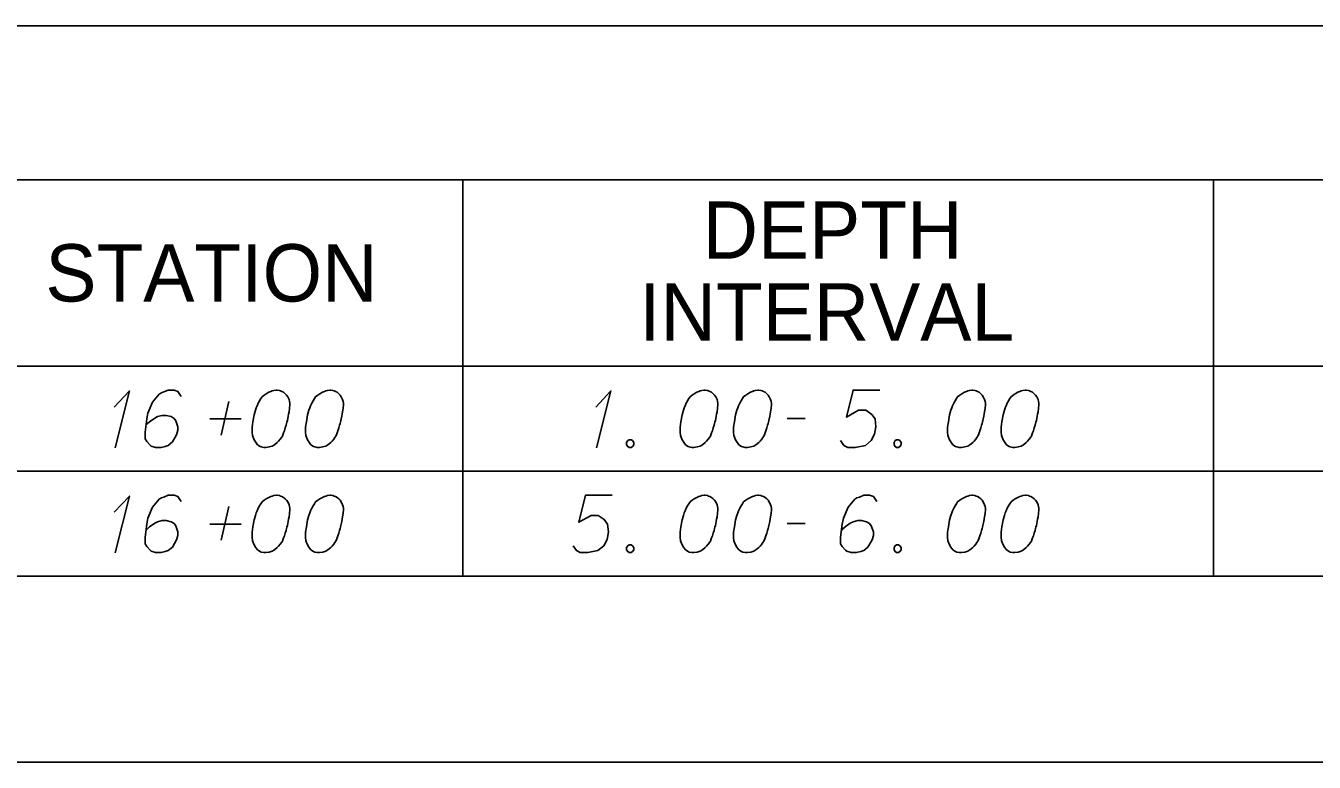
# Model space of a CAD drawing. Extents: x 2074207 to 2076812, y 516372 to 523312.
# Drawn here: x 2076345.6 to 2076453.5, y 516524.4 to 516586.1 of the extents above; entities that cross this region are included whole.
import ezdxf

# ---------------------------------------------------------------- set-up
doc = ezdxf.new("R2010")
doc.units = 0
for name, color, linetype in [('Prop DirtTable_ Soil Test Results - Outline (Major)', 7, 'Continuous'), ('Prop DirtTable_ Soil Test Results - Outline (Minor)', 7, 'Continuous'), ('Prop DirtTable_ Soil Test Results - Tx (Header - Small)', 7, 'Continuous'), ('Prop DirtTable_ Soil Test Results - Tx (Sample Data)', 7, 'Continuous')]:
    doc.layers.add(name, color=color, linetype=linetype)

msp = doc.modelspace()

# ---------------------------------------------------------------- linework, layer by layer
at = {"layer": 'Prop DirtTable_ Soil Test Results - Outline (Major)'}
for p, q in [((2076260.61, 516586.09), (2076811.9, 516586.09)), ((2076260.61, 516557.6), (2076811.9, 516557.6)), ((2076260.61, 516557.6), (2076811.9, 516557.6)), ((2076260.61, 516540), (2076811.9, 516540)), ((2076260.61, 516524.42), (2076811.9, 516524.42))]:
    msp.add_line(p, q, dxfattribs=at)
at = {"layer": 'Prop DirtTable_ Soil Test Results - Outline (Minor)'}
for p, q in [((2076260.61, 516573.2), (2076811.9, 516573.2)), ((2076382.2, 516573.2), (2076382.2, 516548.8)), ((2076445.06, 516573.2), (2076445.06, 516548.8)), ((2076260.61, 516548.8), (2076811.9, 516548.8)), ((2076260.61, 516548.8), (2076811.9, 516548.8)), ((2076382.2, 516548.8), (2076382.2, 516540)), ((2076445.06, 516548.8), (2076445.06, 516540)), ((2076260.61, 516540), (2076811.9, 516540))]:
    msp.add_line(p, q, dxfattribs=at)
at = {"layer": 'Prop DirtTable_ Soil Test Results - Tx (Sample Data)'}
for points in [[(2076353.02, 516554.15), (2076354.29, 516555.51), (2076353.09, 516550.75)], [(2076358.63, 516555.06), (2076358.35, 516555.47), (2076358.03, 516555.59), (2076357.54, 516555.59), (2076357.18, 516555.43), (2076356.97, 516555.36), (2076356.79, 516555.25), (2076356.23, 516554.57), (2076355.84, 516553.66), (2076355.74, 516553.17), (2076355.6, 516552.07), (2076355.6, 516551.5), (2076355.74, 516551.28), (2076356.02, 516550.98), (2076356.12, 516550.9), (2076356.48, 516550.79), (2076356.94, 516550.79), (2076357.29, 516550.86), (2076357.54, 516550.94), (2076357.89, 516551.24), (2076358.24, 516551.84), (2076358.35, 516552.22), (2076358.35, 516552.52), (2076358.17, 516553.02), (2076358.03, 516553.21), (2076357.78, 516553.36), (2076357.36, 516553.47), (2076357.04, 516553.47), (2076356.65, 516553.36), (2076356.41, 516553.24), (2076355.98, 516552.94), (2076355.77, 516552.75), (2076355.67, 516552.64)], [(2076366.67, 516555.59), (2076366.6, 516555.59), (2076366.39, 516555.55), (2076366.25, 516555.51), (2076366.14, 516555.47), (2076365.97, 516555.4), (2076365.75, 516555.28), (2076365.58, 516555.17), (2076365.4, 516555.02), (2076365.3, 516554.87), (2076365.19, 516554.68), (2076365.08, 516554.49), (2076364.98, 516554.26), (2076364.91, 516554.11), (2076364.84, 516553.89), (2076364.73, 516553.51), (2076364.63, 516552.94), (2076364.56, 516552.49), (2076364.56, 516552.07), (2076364.59, 516551.77), (2076364.73, 516551.43), (2076364.84, 516551.24), (2076365.01, 516551.01), (2076365.23, 516550.86), (2076365.33, 516550.82), (2076365.54, 516550.79), (2076365.72, 516550.79), (2076366, 516550.82), (2076366.25, 516550.9), (2076366.43, 516551.01), (2076366.67, 516551.2), (2076366.78, 516551.32), (2076366.92, 516551.47), (2076367.02, 516551.62), (2076367.1, 516551.73), (2076367.17, 516551.92), (2076367.2, 516552), (2076367.27, 516552.18), (2076367.34, 516552.41), (2076367.41, 516552.64), (2076367.45, 516552.79), (2076367.48, 516552.9), (2076367.52, 516553.05), (2076367.59, 516553.39), (2076367.62, 516553.58), (2076367.66, 516553.77), (2076367.7, 516554.04), (2076367.73, 516554.38), (2076367.73, 516554.49), (2076367.7, 516554.64), (2076367.66, 516554.79), (2076367.55, 516555.02), (2076367.45, 516555.17), (2076367.34, 516555.28), (2076367.2, 516555.4), (2076367.06, 516555.47), (2076366.95, 516555.51), (2076366.85, 516555.55), (2076366.67, 516555.59)], [(2076371.15, 516555.59), (2076371.08, 516555.59), (2076370.87, 516555.55), (2076370.73, 516555.51), (2076370.62, 516555.47), (2076370.45, 516555.4), (2076370.23, 516555.28), (2076370.06, 516555.17), (2076369.88, 516555.02), (2076369.78, 516554.87), (2076369.67, 516554.68), (2076369.56, 516554.49), (2076369.46, 516554.26), (2076369.39, 516554.11), (2076369.32, 516553.89), (2076369.21, 516553.51), (2076369.11, 516552.94), (2076369.04, 516552.49), (2076369.04, 516552.07), (2076369.07, 516551.77), (2076369.21, 516551.43), (2076369.32, 516551.24), (2076369.49, 516551.01), (2076369.71, 516550.86), (2076369.81, 516550.82), (2076370.02, 516550.79), (2076370.2, 516550.79), (2076370.48, 516550.82), (2076370.73, 516550.9), (2076370.91, 516551.01), (2076371.15, 516551.2), (2076371.26, 516551.32), (2076371.4, 516551.47), (2076371.5, 516551.62), (2076371.58, 516551.73), (2076371.65, 516551.92), (2076371.68, 516552), (2076371.75, 516552.18), (2076371.82, 516552.41), (2076371.89, 516552.64), (2076371.93, 516552.79), (2076371.96, 516552.9), (2076372, 516553.05), (2076372.07, 516553.39), (2076372.1, 516553.58), (2076372.14, 516553.77), (2076372.18, 516554.04), (2076372.21, 516554.38), (2076372.21, 516554.49), (2076372.18, 516554.64), (2076372.14, 516554.79), (2076372.03, 516555.02), (2076371.93, 516555.17), (2076371.82, 516555.28), (2076371.68, 516555.4), (2076371.54, 516555.47), (2076371.43, 516555.51), (2076371.33, 516555.55), (2076371.15, 516555.59)], [(2076393.34, 516554.15), (2076394.61, 516555.51), (2076393.41, 516550.75)], [(2076402.51, 516555.59), (2076402.44, 516555.59), (2076402.23, 516555.55), (2076402.09, 516555.51), (2076401.98, 516555.47), (2076401.81, 516555.4), (2076401.59, 516555.28), (2076401.42, 516555.17), (2076401.24, 516555.02), (2076401.14, 516554.87), (2076401.03, 516554.68), (2076400.92, 516554.49), (2076400.82, 516554.26), (2076400.75, 516554.11), (2076400.68, 516553.89), (2076400.57, 516553.51), (2076400.47, 516552.94), (2076400.4, 516552.49), (2076400.4, 516552.07), (2076400.43, 516551.77), (2076400.57, 516551.43), (2076400.68, 516551.24), (2076400.85, 516551.01), (2076401.07, 516550.86), (2076401.17, 516550.82), (2076401.38, 516550.79), (2076401.56, 516550.79), (2076401.84, 516550.82), (2076402.09, 516550.9), (2076402.27, 516551.01), (2076402.51, 516551.2), (2076402.62, 516551.32), (2076402.76, 516551.47), (2076402.86, 516551.62), (2076402.94, 516551.73), (2076403.01, 516551.92), (2076403.04, 516552), (2076403.11, 516552.18), (2076403.18, 516552.41), (2076403.25, 516552.64), (2076403.29, 516552.79), (2076403.32, 516552.9), (2076403.36, 516553.05), (2076403.43, 516553.39), (2076403.46, 516553.58), (2076403.5, 516553.77), (2076403.54, 516554.04), (2076403.57, 516554.38), (2076403.57, 516554.49), (2076403.54, 516554.64), (2076403.5, 516554.79), (2076403.39, 516555.02), (2076403.29, 516555.17), (2076403.18, 516555.28), (2076403.04, 516555.4), (2076402.9, 516555.47), (2076402.79, 516555.51), (2076402.69, 516555.55), (2076402.51, 516555.59)], [(2076406.99, 516555.59), (2076406.92, 516555.59), (2076406.71, 516555.55), (2076406.57, 516555.51), (2076406.46, 516555.47), (2076406.29, 516555.4), (2076406.07, 516555.28), (2076405.9, 516555.17), (2076405.72, 516555.02), (2076405.62, 516554.87), (2076405.51, 516554.68), (2076405.4, 516554.49), (2076405.3, 516554.26), (2076405.23, 516554.11), (2076405.16, 516553.89), (2076405.05, 516553.51), (2076404.95, 516552.94), (2076404.88, 516552.49), (2076404.88, 516552.07), (2076404.91, 516551.77), (2076405.05, 516551.43), (2076405.16, 516551.24), (2076405.33, 516551.01), (2076405.55, 516550.86), (2076405.65, 516550.82), (2076405.86, 516550.79), (2076406.04, 516550.79), (2076406.32, 516550.82), (2076406.57, 516550.9), (2076406.75, 516551.01), (2076406.99, 516551.2), (2076407.1, 516551.32), (2076407.24, 516551.47), (2076407.34, 516551.62), (2076407.42, 516551.73), (2076407.49, 516551.92), (2076407.52, 516552), (2076407.59, 516552.18), (2076407.66, 516552.41), (2076407.73, 516552.64), (2076407.77, 516552.79), (2076407.8, 516552.9), (2076407.84, 516553.05), (2076407.91, 516553.39), (2076407.94, 516553.58), (2076407.98, 516553.77), (2076408.02, 516554.04), (2076408.05, 516554.38), (2076408.05, 516554.49), (2076408.02, 516554.64), (2076407.98, 516554.79), (2076407.87, 516555.02), (2076407.77, 516555.17), (2076407.66, 516555.28), (2076407.52, 516555.4), (2076407.38, 516555.47), (2076407.27, 516555.51), (2076407.17, 516555.55), (2076406.99, 516555.59)], [(2076417.12, 516555.59), (2076414.89, 516555.59), (2076414.33, 516553.32), (2076415.35, 516553.89), (2076415.95, 516553.89), (2076416.45, 516553.55), (2076416.73, 516553.17), (2076416.8, 516552.52), (2076416.69, 516551.88), (2076416.41, 516551.35), (2076415.92, 516550.94), (2076415.07, 516550.79), (2076414.44, 516550.79), (2076414.12, 516550.94), (2076413.84, 516551.35)], [(2076424.91, 516555.59), (2076424.84, 516555.59), (2076424.63, 516555.55), (2076424.49, 516555.51), (2076424.38, 516555.47), (2076424.21, 516555.4), (2076423.99, 516555.28), (2076423.82, 516555.17), (2076423.64, 516555.02), (2076423.54, 516554.87), (2076423.43, 516554.68), (2076423.32, 516554.49), (2076423.22, 516554.26), (2076423.15, 516554.11), (2076423.08, 516553.89), (2076422.97, 516553.51), (2076422.87, 516552.94), (2076422.8, 516552.49), (2076422.8, 516552.07), (2076422.83, 516551.77), (2076422.97, 516551.43), (2076423.08, 516551.24), (2076423.25, 516551.01), (2076423.47, 516550.86), (2076423.57, 516550.82), (2076423.78, 516550.79), (2076423.96, 516550.79), (2076424.24, 516550.82), (2076424.49, 516550.9), (2076424.67, 516551.01), (2076424.91, 516551.2), (2076425.02, 516551.32), (2076425.16, 516551.47), (2076425.26, 516551.62), (2076425.34, 516551.73), (2076425.41, 516551.92), (2076425.44, 516552), (2076425.51, 516552.18), (2076425.58, 516552.41), (2076425.65, 516552.64), (2076425.69, 516552.79), (2076425.72, 516552.9), (2076425.76, 516553.05), (2076425.83, 516553.39), (2076425.86, 516553.58), (2076425.9, 516553.77), (2076425.94, 516554.04), (2076425.97, 516554.38), (2076425.97, 516554.49), (2076425.94, 516554.64), (2076425.9, 516554.79), (2076425.79, 516555.02), (2076425.69, 516555.17), (2076425.58, 516555.28), (2076425.44, 516555.4), (2076425.3, 516555.47), (2076425.19, 516555.51), (2076425.09, 516555.55), (2076424.91, 516555.59)], [(2076429.39, 516555.59), (2076429.32, 516555.59), (2076429.11, 516555.55), (2076428.97, 516555.51), (2076428.86, 516555.47), (2076428.69, 516555.4), (2076428.47, 516555.28), (2076428.3, 516555.17), (2076428.12, 516555.02), (2076428.02, 516554.87), (2076427.91, 516554.68), (2076427.8, 516554.49), (2076427.7, 516554.26), (2076427.63, 516554.11), (2076427.56, 516553.89), (2076427.45, 516553.51), (2076427.35, 516552.94), (2076427.28, 516552.49), (2076427.28, 516552.07), (2076427.31, 516551.77), (2076427.45, 516551.43), (2076427.56, 516551.24), (2076427.73, 516551.01), (2076427.95, 516550.86), (2076428.05, 516550.82), (2076428.26, 516550.79), (2076428.44, 516550.79), (2076428.72, 516550.82), (2076428.97, 516550.9), (2076429.15, 516551.01), (2076429.39, 516551.2), (2076429.5, 516551.32), (2076429.64, 516551.47), (2076429.74, 516551.62), (2076429.82, 516551.73), (2076429.89, 516551.92), (2076429.92, 516552), (2076429.99, 516552.18), (2076430.06, 516552.41), (2076430.13, 516552.64), (2076430.17, 516552.79), (2076430.2, 516552.9), (2076430.24, 516553.05), (2076430.31, 516553.39), (2076430.34, 516553.58), (2076430.38, 516553.77), (2076430.42, 516554.04), (2076430.45, 516554.38), (2076430.45, 516554.49), (2076430.42, 516554.64), (2076430.38, 516554.79), (2076430.27, 516555.02), (2076430.17, 516555.17), (2076430.06, 516555.28), (2076429.92, 516555.4), (2076429.78, 516555.47), (2076429.67, 516555.51), (2076429.57, 516555.55), (2076429.39, 516555.59)], [(2076361.98, 516551.81), (2076362.62, 516554.64)], [(2076361.03, 516553.17), (2076363.64, 516553.17)], [(2076409.36, 516553.21), (2076410.87, 516553.21)], [(2076396.13, 516551.43), (2076396.3, 516551.43), (2076396.41, 516551.35), (2076396.52, 516551.2), (2076396.52, 516551.01), (2076396.41, 516550.86), (2076396.3, 516550.79), (2076396.13, 516550.79), (2076396.02, 516550.86), (2076395.92, 516551.01), (2076395.92, 516551.2), (2076396.02, 516551.35), (2076396.13, 516551.43)], [(2076418.53, 516551.43), (2076418.7, 516551.43), (2076418.81, 516551.35), (2076418.92, 516551.2), (2076418.92, 516551.01), (2076418.81, 516550.86), (2076418.7, 516550.79), (2076418.53, 516550.79), (2076418.42, 516550.86), (2076418.32, 516551.01), (2076418.32, 516551.2), (2076418.42, 516551.35), (2076418.53, 516551.43)], [(2076353.02, 516545.35), (2076354.29, 516546.71), (2076353.09, 516541.95)], [(2076358.63, 516546.26), (2076358.35, 516546.67), (2076358.03, 516546.79), (2076357.54, 516546.79), (2076357.18, 516546.63), (2076356.97, 516546.56), (2076356.79, 516546.45), (2076356.23, 516545.77), (2076355.84, 516544.86), (2076355.74, 516544.37), (2076355.6, 516543.27), (2076355.6, 516542.7), (2076355.74, 516542.48), (2076356.02, 516542.18), (2076356.12, 516542.1), (2076356.48, 516541.99), (2076356.94, 516541.99), (2076357.29, 516542.06), (2076357.54, 516542.14), (2076357.89, 516542.44), (2076358.24, 516543.04), (2076358.35, 516543.42), (2076358.35, 516543.72), (2076358.17, 516544.22), (2076358.03, 516544.41), (2076357.78, 516544.56), (2076357.36, 516544.67), (2076357.04, 516544.67), (2076356.65, 516544.56), (2076356.41, 516544.44), (2076355.98, 516544.14), (2076355.77, 516543.95), (2076355.67, 516543.84)], [(2076366.67, 516546.79), (2076366.6, 516546.79), (2076366.39, 516546.75), (2076366.25, 516546.71), (2076366.14, 516546.67), (2076365.97, 516546.6), (2076365.75, 516546.48), (2076365.58, 516546.37), (2076365.4, 516546.22), (2076365.3, 516546.07), (2076365.19, 516545.88), (2076365.08, 516545.69), (2076364.98, 516545.46), (2076364.91, 516545.31), (2076364.84, 516545.09), (2076364.73, 516544.71), (2076364.63, 516544.14), (2076364.56, 516543.69), (2076364.56, 516543.27), (2076364.59, 516542.97), (2076364.73, 516542.63), (2076364.84, 516542.44), (2076365.01, 516542.21), (2076365.23, 516542.06), (2076365.33, 516542.02), (2076365.54, 516541.99), (2076365.72, 516541.99), (2076366, 516542.02), (2076366.25, 516542.1), (2076366.43, 516542.21), (2076366.67, 516542.4), (2076366.78, 516542.52), (2076366.92, 516542.67), (2076367.02, 516542.82), (2076367.1, 516542.93), (2076367.17, 516543.12), (2076367.2, 516543.2), (2076367.27, 516543.38), (2076367.34, 516543.61), (2076367.41, 516543.84), (2076367.45, 516543.99), (2076367.48, 516544.1), (2076367.52, 516544.25), (2076367.59, 516544.59), (2076367.62, 516544.78), (2076367.66, 516544.97), (2076367.7, 516545.24), (2076367.73, 516545.58), (2076367.73, 516545.69), (2076367.7, 516545.84), (2076367.66, 516545.99), (2076367.55, 516546.22), (2076367.45, 516546.37), (2076367.34, 516546.48), (2076367.2, 516546.6), (2076367.06, 516546.67), (2076366.95, 516546.71), (2076366.85, 516546.75), (2076366.67, 516546.79)], [(2076371.15, 516546.79), (2076371.08, 516546.79), (2076370.87, 516546.75), (2076370.73, 516546.71), (2076370.62, 516546.67), (2076370.45, 516546.6), (2076370.23, 516546.48), (2076370.06, 516546.37), (2076369.88, 516546.22), (2076369.78, 516546.07), (2076369.67, 516545.88), (2076369.56, 516545.69), (2076369.46, 516545.46), (2076369.39, 516545.31), (2076369.32, 516545.09), (2076369.21, 516544.71), (2076369.11, 516544.14), (2076369.04, 516543.69), (2076369.04, 516543.27), (2076369.07, 516542.97), (2076369.21, 516542.63), (2076369.32, 516542.44), (2076369.49, 516542.21), (2076369.71, 516542.06), (2076369.81, 516542.02), (2076370.02, 516541.99), (2076370.2, 516541.99), (2076370.48, 516542.02), (2076370.73, 516542.1), (2076370.91, 516542.21), (2076371.15, 516542.4), (2076371.26, 516542.52), (2076371.4, 516542.67), (2076371.5, 516542.82), (2076371.58, 516542.93), (2076371.65, 516543.12), (2076371.68, 516543.2), (2076371.75, 516543.38), (2076371.82, 516543.61), (2076371.89, 516543.84), (2076371.93, 516543.99), (2076371.96, 516544.1), (2076372, 516544.25), (2076372.07, 516544.59), (2076372.1, 516544.78), (2076372.14, 516544.97), (2076372.18, 516545.24), (2076372.21, 516545.58), (2076372.21, 516545.69), (2076372.18, 516545.84), (2076372.14, 516545.99), (2076372.03, 516546.22), (2076371.93, 516546.37), (2076371.82, 516546.48), (2076371.68, 516546.6), (2076371.54, 516546.67), (2076371.43, 516546.71), (2076371.33, 516546.75), (2076371.15, 516546.79)], [(2076394.72, 516546.79), (2076392.49, 516546.79), (2076391.93, 516544.52), (2076392.95, 516545.09), (2076393.55, 516545.09), (2076394.05, 516544.75), (2076394.33, 516544.37), (2076394.4, 516543.72), (2076394.29, 516543.08), (2076394.01, 516542.55), (2076393.52, 516542.14), (2076392.67, 516541.99), (2076392.04, 516541.99), (2076391.72, 516542.14), (2076391.44, 516542.55)], [(2076402.51, 516546.79), (2076402.44, 516546.79), (2076402.23, 516546.75), (2076402.09, 516546.71), (2076401.98, 516546.67), (2076401.81, 516546.6), (2076401.59, 516546.48), (2076401.42, 516546.37), (2076401.24, 516546.22), (2076401.14, 516546.07), (2076401.03, 516545.88), (2076400.92, 516545.69), (2076400.82, 516545.46), (2076400.75, 516545.31), (2076400.68, 516545.09), (2076400.57, 516544.71), (2076400.47, 516544.14), (2076400.4, 516543.69), (2076400.4, 516543.27), (2076400.43, 516542.97), (2076400.57, 516542.63), (2076400.68, 516542.44), (2076400.85, 516542.21), (2076401.07, 516542.06), (2076401.17, 516542.02), (2076401.38, 516541.99), (2076401.56, 516541.99), (2076401.84, 516542.02), (2076402.09, 516542.1), (2076402.27, 516542.21), (2076402.51, 516542.4), (2076402.62, 516542.52), (2076402.76, 516542.67), (2076402.86, 516542.82), (2076402.94, 516542.93), (2076403.01, 516543.12), (2076403.04, 516543.2), (2076403.11, 516543.38), (2076403.18, 516543.61), (2076403.25, 516543.84), (2076403.29, 516543.99), (2076403.32, 516544.1), (2076403.36, 516544.25), (2076403.43, 516544.59), (2076403.46, 516544.78), (2076403.5, 516544.97), (2076403.54, 516545.24), (2076403.57, 516545.58), (2076403.57, 516545.69), (2076403.54, 516545.84), (2076403.5, 516545.99), (2076403.39, 516546.22), (2076403.29, 516546.37), (2076403.18, 516546.48), (2076403.04, 516546.6), (2076402.9, 516546.67), (2076402.79, 516546.71), (2076402.69, 516546.75), (2076402.51, 516546.79)], [(2076406.99, 516546.79), (2076406.92, 516546.79), (2076406.71, 516546.75), (2076406.57, 516546.71), (2076406.46, 516546.67), (2076406.29, 516546.6), (2076406.07, 516546.48), (2076405.9, 516546.37), (2076405.72, 516546.22), (2076405.62, 516546.07), (2076405.51, 516545.88), (2076405.4, 516545.69), (2076405.3, 516545.46), (2076405.23, 516545.31), (2076405.16, 516545.09), (2076405.05, 516544.71), (2076404.95, 516544.14), (2076404.88, 516543.69), (2076404.88, 516543.27), (2076404.91, 516542.97), (2076405.05, 516542.63), (2076405.16, 516542.44), (2076405.33, 516542.21), (2076405.55, 516542.06), (2076405.65, 516542.02), (2076405.86, 516541.99), (2076406.04, 516541.99), (2076406.32, 516542.02), (2076406.57, 516542.1), (2076406.75, 516542.21), (2076406.99, 516542.4), (2076407.1, 516542.52), (2076407.24, 516542.67), (2076407.34, 516542.82), (2076407.42, 516542.93), (2076407.49, 516543.12), (2076407.52, 516543.2), (2076407.59, 516543.38), (2076407.66, 516543.61), (2076407.73, 516543.84), (2076407.77, 516543.99), (2076407.8, 516544.1), (2076407.84, 516544.25), (2076407.91, 516544.59), (2076407.94, 516544.78), (2076407.98, 516544.97), (2076408.02, 516545.24), (2076408.05, 516545.58), (2076408.05, 516545.69), (2076408.02, 516545.84), (2076407.98, 516545.99), (2076407.87, 516546.22), (2076407.77, 516546.37), (2076407.66, 516546.48), (2076407.52, 516546.6), (2076407.38, 516546.67), (2076407.27, 516546.71), (2076407.17, 516546.75), (2076406.99, 516546.79)], [(2076416.87, 516546.26), (2076416.59, 516546.67), (2076416.27, 516546.79), (2076415.78, 516546.79), (2076415.42, 516546.63), (2076415.21, 516546.56), (2076415.03, 516546.45), (2076414.47, 516545.77), (2076414.08, 516544.86), (2076413.98, 516544.37), (2076413.84, 516543.27), (2076413.84, 516542.7), (2076413.98, 516542.48), (2076414.26, 516542.18), (2076414.36, 516542.1), (2076414.72, 516541.99), (2076415.18, 516541.99), (2076415.53, 516542.06), (2076415.78, 516542.14), (2076416.13, 516542.44), (2076416.48, 516543.04), (2076416.59, 516543.42), (2076416.59, 516543.72), (2076416.41, 516544.22), (2076416.27, 516544.41), (2076416.02, 516544.56), (2076415.6, 516544.67), (2076415.28, 516544.67), (2076414.89, 516544.56), (2076414.65, 516544.44), (2076414.22, 516544.14), (2076414.01, 516543.95), (2076413.91, 516543.84)], [(2076424.91, 516546.79), (2076424.84, 516546.79), (2076424.63, 516546.75), (2076424.49, 516546.71), (2076424.38, 516546.67), (2076424.21, 516546.6), (2076423.99, 516546.48), (2076423.82, 516546.37), (2076423.64, 516546.22), (2076423.54, 516546.07), (2076423.43, 516545.88), (2076423.32, 516545.69), (2076423.22, 516545.46), (2076423.15, 516545.31), (2076423.08, 516545.09), (2076422.97, 516544.71), (2076422.87, 516544.14), (2076422.8, 516543.69), (2076422.8, 516543.27), (2076422.83, 516542.97), (2076422.97, 516542.63), (2076423.08, 516542.44), (2076423.25, 516542.21), (2076423.47, 516542.06), (2076423.57, 516542.02), (2076423.78, 516541.99), (2076423.96, 516541.99), (2076424.24, 516542.02), (2076424.49, 516542.1), (2076424.67, 516542.21), (2076424.91, 516542.4), (2076425.02, 516542.52), (2076425.16, 516542.67), (2076425.26, 516542.82), (2076425.34, 516542.93), (2076425.41, 516543.12), (2076425.44, 516543.2), (2076425.51, 516543.38), (2076425.58, 516543.61), (2076425.65, 516543.84), (2076425.69, 516543.99), (2076425.72, 516544.1), (2076425.76, 516544.25), (2076425.83, 516544.59), (2076425.86, 516544.78), (2076425.9, 516544.97), (2076425.94, 516545.24), (2076425.97, 516545.58), (2076425.97, 516545.69), (2076425.94, 516545.84), (2076425.9, 516545.99), (2076425.79, 516546.22), (2076425.69, 516546.37), (2076425.58, 516546.48), (2076425.44, 516546.6), (2076425.3, 516546.67), (2076425.19, 516546.71), (2076425.09, 516546.75), (2076424.91, 516546.79)], [(2076429.39, 516546.79), (2076429.32, 516546.79), (2076429.11, 516546.75), (2076428.97, 516546.71), (2076428.86, 516546.67), (2076428.69, 516546.6), (2076428.47, 516546.48), (2076428.3, 516546.37), (2076428.12, 516546.22), (2076428.02, 516546.07), (2076427.91, 516545.88), (2076427.8, 516545.69), (2076427.7, 516545.46), (2076427.63, 516545.31), (2076427.56, 516545.09), (2076427.45, 516544.71), (2076427.35, 516544.14), (2076427.28, 516543.69), (2076427.28, 516543.27), (2076427.31, 516542.97), (2076427.45, 516542.63), (2076427.56, 516542.44), (2076427.73, 516542.21), (2076427.95, 516542.06), (2076428.05, 516542.02), (2076428.26, 516541.99), (2076428.44, 516541.99), (2076428.72, 516542.02), (2076428.97, 516542.1), (2076429.15, 516542.21), (2076429.39, 516542.4), (2076429.5, 516542.52), (2076429.64, 516542.67), (2076429.74, 516542.82), (2076429.82, 516542.93), (2076429.89, 516543.12), (2076429.92, 516543.2), (2076429.99, 516543.38), (2076430.06, 516543.61), (2076430.13, 516543.84), (2076430.17, 516543.99), (2076430.2, 516544.1), (2076430.24, 516544.25), (2076430.31, 516544.59), (2076430.34, 516544.78), (2076430.38, 516544.97), (2076430.42, 516545.24), (2076430.45, 516545.58), (2076430.45, 516545.69), (2076430.42, 516545.84), (2076430.38, 516545.99), (2076430.27, 516546.22), (2076430.17, 516546.37), (2076430.06, 516546.48), (2076429.92, 516546.6), (2076429.78, 516546.67), (2076429.67, 516546.71), (2076429.57, 516546.75), (2076429.39, 516546.79)], [(2076361.98, 516543.01), (2076362.62, 516545.84)], [(2076409.36, 516544.41), (2076410.87, 516544.41)], [(2076361.03, 516544.37), (2076363.64, 516544.37)], [(2076396.13, 516542.63), (2076396.3, 516542.63), (2076396.41, 516542.55), (2076396.52, 516542.4), (2076396.52, 516542.21), (2076396.41, 516542.06), (2076396.3, 516541.99), (2076396.13, 516541.99), (2076396.02, 516542.06), (2076395.92, 516542.21), (2076395.92, 516542.4), (2076396.02, 516542.55), (2076396.13, 516542.63)], [(2076418.53, 516542.63), (2076418.7, 516542.63), (2076418.81, 516542.55), (2076418.92, 516542.4), (2076418.92, 516542.21), (2076418.81, 516542.06), (2076418.7, 516541.99), (2076418.53, 516541.99), (2076418.42, 516542.06), (2076418.32, 516542.21), (2076418.32, 516542.4), (2076418.42, 516542.55), (2076418.53, 516542.63)]]:
    msp.add_lwpolyline(points, dxfattribs=at)

# ---------------------------------------------------------------- texts
at = {"layer": 'Prop DirtTable_ Soil Test Results - Tx (Header - Small)'}
for s, p in [('DEPTH', (2076402.29, 516566.59)), ('STATION', (2076347.25, 516563)), ('INTERVAL', (2076396.98, 516559.73))]:
    msp.add_text(s, height=4.8, dxfattribs=at).set_placement(p)

doc.saveas('drawing.dxf')
